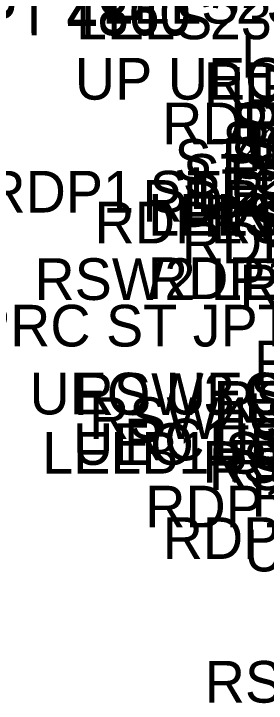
# Model space of a CAD drawing. Extents: x 1040177 to 1042343, y 1125540 to 1129143.
# Drawn here: x 1041423.2 to 1041483.7, y 1125863.2 to 1126028.6 of the extents above; entities that cross this region are included whole.
import ezdxf

# ---------------------------------------------------------------- set-up
doc = ezdxf.new("R2010")
doc.units = 0
for name, color, linetype in [('CDEFAULT', 7, 'Continuous'), ('COCOD', 7, 'Continuous'), ('COELE', 7, 'Continuous'), ('COPNT', 7, 'Continuous'), ('RDP', 7, 'Continuous')]:
    doc.layers.add(name, color=color, linetype=linetype)

msp = doc.modelspace()

# ---------------------------------------------------------------- linework, layer by layer
at = {"layer": 'RDP'}
msp.add_lwpolyline([(1041475.8, 1125990.93), (1041490.02, 1126007.3), (1041500.05, 1126016.99)], dxfattribs=at)

# ---------------------------------------------------------------- texts
at = {"layer": 'CDEFAULT'}
for height, p in [(10, (1041472.54, 1125985.93)), (0.0781, (1041475.78, 1125990.89))]:
    msp.add_text('+', height=height, dxfattribs=at).set_placement(p)
at = {"layer": 'COCOD'}
for s, height, p in [('LELS', 10, (1041444.35, 1126026.26)), ('UPGW ST JPT 4860', 10, (1041342.23, 1126023.97)), ('UPGW ST JPT 4860', 10, (1041342.28, 1126023.43)), ('LELS', 10, (1041438.1, 1126022.51)), ('LELB1 CL', 10, (1041477.7, 1126013.28)), ('UP UEO', 10, (1041437.83, 1126008.02)), ('RDP1', 10, (1041468.79, 1126006.99)), ('LELB1 ST', 10, (1041475.06, 1126005.82)), ('RDP1', 10, (1041458.76, 1125997.3)), ('STSEW2', 10, (1041475.59, 1125997.35)), ('PSU1 ST', 10, (1041475.28, 1125997.23)), ('STFBY1', 10, (1041473.19, 1125992.8)), ('STSEW2', 10, (1041478.23, 1125992.05)), ('LELB1 CL', 10, (1041480.07, 1125991.28)), ('STSEW1', 10, (1041461.73, 1125988.57)), ('STFBY1', 10, (1041475.22, 1125989.06)), ('STSEW1', 10, (1041463.74, 1125984.96)), ('RDP1 ST', 10, (1041416.36, 1125980.93)), ('LELS', 10, (1041465.3, 1125981.76)), ('RDP1 ST', 0.0781, (1041475.45, 1125990.85)), ('RDP1 ST', 10, (1041454.03, 1125978.7)), ('LELS', 10, (1041455.43, 1125975.35)), ('RSW2', 10, (1041468.72, 1125975.14)), ('RDP1', 10, (1041475.13, 1125975.77)), ('RDP1 PC', 10, (1041442.54, 1125973.51)), ('RSW1', 10, (1041470.45, 1125973.52)), ('RDP1', 10, (1041463.46, 1125968.71)), ('RSW2 LELB1', 10, (1041428.13, 1125959.95)), ('RDP1', 10, (1041455.36, 1125960.16)), ('RSW1', 10, (1041477.31, 1125958.45)), ('PRC ST JPT 2164', 10, (1041413.37, 1125948.78)), ('RSW3', 10, (1041480.8, 1125940.21)), ('UEO UEO2 ST', 10, (1041426.96, 1125932.48)), ('RSW3 ST', 10, (1041437.55, 1125932.36)), ('LELS', 10, (1041471.1, 1125930.5)), ('RSW4', 10, (1041471.43, 1125930.47)), ('RSW4 ST', 10, (1041441.23, 1125926.6)), ('UEO2', 10, (1041479.19, 1125927.53)), ('RC1 ST RDP1', 10, (1041449.61, 1125921.46)), ('UEO UEO1 ST', 10, (1041437.38, 1125920.38)), ('LELB1 ST RDP1', 10, (1041429.98, 1125918.27)), ('RDP1 PC', 10, (1041474.55, 1125916.33)), ('RSW2 ST', 10, (1041468.44, 1125916.07)), ('RSW1 ST', 10, (1041469.98, 1125914.32)), ('RDP1 PC', 10, (1041480.23, 1125907.95)), ('RDP1 ST', 10, (1041454.71, 1125905.37)), ('RDP1 ST', 10, (1041458.9, 1125897.8)), ('UEO UEO1', 10, (1041478.47, 1125894.81)), ('RSW3 ST', 10, (1041468.99, 1125863.32))]:
    msp.add_text(s, height=height, dxfattribs=at).set_placement(p)
at = {"layer": 'COELE'}
for height in [10, 0.0781]:
    msp.add_text('409.119', height=height, dxfattribs=at).set_placement((1041475.8, 1125990.93))
at = {"layer": 'COPNT'}
for s, height, p in [('2398', 10, (1041476.47, 1126026.26)), ('2399', 10, (1041470.22, 1126022.51)), ('2391', 10, (1041475.8, 1125980.93)), ('2391', 0.0781, (1041475.8, 1125990.85))]:
    msp.add_text(s, height=height, dxfattribs=at).set_placement(p)

doc.saveas('drawing.dxf')
